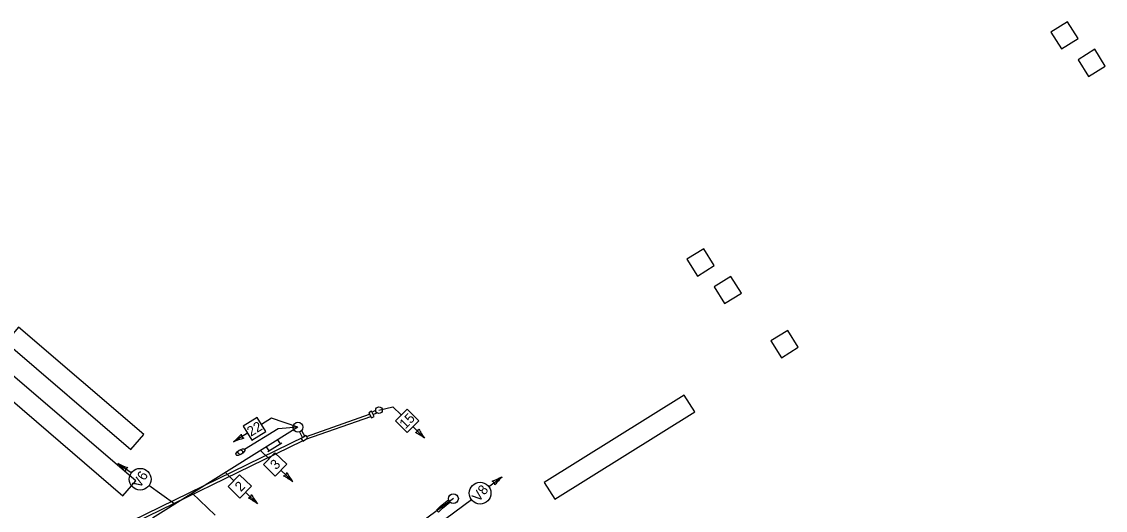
# Model space of a CAD drawing. Extents: x 982100 to 1292532, y 220574 to 1843876.
# Drawn here: x 984464.9 to 984793.2, y 1843411.6 to 1843559.9 of the extents above; entities that cross this region are included whole.
import ezdxf

# ---------------------------------------------------------------- set-up
doc = ezdxf.new("R2010")
doc.units = 0
for name, color, linetype in [('5', 7, 'Continuous'), ('R_Existing Signal', 7, 'Continuous'), ('R_Existing Signal Mast Arm', 7, 'Continuous'), ('V-SIGNAL-CONDUIT', 7, 'Continuous'), ('V-SIGNAL-HEAD', 7, 'Continuous'), ('V-SIGNAL-LOOP', 7, 'Continuous'), ('V-SIGNAL-MAST', 7, 'Continuous')]:
    doc.layers.add(name, color=color, linetype=linetype)

msp = doc.modelspace()

# ---------------------------------------------------------------- linework, layer by layer
at = {"layer": '5'}
msp.add_line((984548.62, 1843436.87), (984504.52, 1843409.32), dxfattribs=at)
at = {"layer": 'R_Existing Signal'}
for p, q in [((984591.78, 1843412.95), (984590.58, 1843411.68)), ((984592.45, 1843412.32), (984591.78, 1843412.95)), ((984591.84, 1843412.89), (984594.27, 1843414.79)), ((984592.43, 1843412.34), (984594.69, 1843414.11)), ((984590.58, 1843411.68), (984591.25, 1843411.05)), ((984591.25, 1843411.05), (984592.45, 1843412.32))]:
    msp.add_line(p, q, dxfattribs=at)
msp.add_circle((984595.72, 1843415.2), 1.5, dxfattribs=at)
at = {"layer": 'R_Existing Signal Mast Arm'}
msp.add_line((984595.72, 1843415.2), (984568.28, 1843395.12), dxfattribs=at)
msp.add_line((984595.72, 1843415.2), (984568.28, 1843395.12), dxfattribs=at)
at = {"layer": 'V-SIGNAL-CONDUIT'}
for p, q in [((984550.98, 1843433.21), (984570.67, 1843440.09)), ((984551.24, 1843434.09), (984570.33, 1843440.77)), ((984570.9, 1843441.68), (984570.08, 1843441.27)), ((984570.08, 1843441.27), (984570.86, 1843439.71)), ((984570.86, 1843439.71), (984571.68, 1843440.12)), ((984571.68, 1843440.12), (984570.9, 1843441.68)), ((984571.04, 1843441.4), (984572.18, 1843442)), ((984571.4, 1843440.67), (984572.54, 1843441.27)), ((984549.74, 1843435.87), (984550.66, 1843434.09)), ((984466.59, 1843393.05), (984550.6, 1843434.05)), ((984467.04, 1843392.32), (984550.02, 1843432.75)), ((984549.06, 1843435.44), (984549.98, 1843433.66)), ((984551.08, 1843434.35), (984549.59, 1843433.42)), ((984549.59, 1843433.42), (984550.08, 1843432.65)), ((984550.08, 1843432.65), (984551.56, 1843433.57)), ((984551.56, 1843433.57), (984551.08, 1843434.35))]:
    msp.add_line(p, q, dxfattribs=at)
for points in [[(984498.02, 1843430.08), (984501.93, 1843434.63), (984463.99, 1843467.21), (984460.08, 1843462.65)], [(984495.6, 1843416.06), (984499.51, 1843420.62), (984461.57, 1843453.19), (984457.67, 1843448.63)], [(984623.25, 1843420.12), (984626.43, 1843415.03), (984668.84, 1843441.52), (984665.66, 1843446.61)]]:
    msp.add_lwpolyline(points, close=True, dxfattribs=at)
at = {"layer": 'V-SIGNAL-HEAD'}
for p, q in [((984577.37, 1843443.09), (984579.9, 1843440.57)), ((984540.6, 1843439.6), (984537.57, 1843437.71)), ((984542.58, 1843436.42), (984532.47, 1843430.1)), ((984583.45, 1843437.06), (984586.99, 1843433.53)), ((984533.33, 1843435.05), (984529.09, 1843432.41)), ((984537.32, 1843429.81), (984539.88, 1843427.32)), ((984498.12, 1843422.98), (984494.06, 1843425.89)), ((984526.63, 1843423.13), (984529.19, 1843420.64)), ((984543.47, 1843423.83), (984547.05, 1843420.35)), ((984606.46, 1843418.85), (984610.46, 1843421.84)), ((984511.31, 1843413.56), (984503.49, 1843419.15)), ((984516.59, 1843416.86), (984523.51, 1843410.19)), ((984532.77, 1843417.16), (984536.35, 1843413.67)), ((984593.47, 1843409.15), (984601.17, 1843414.9))]:
    msp.add_line(p, q, dxfattribs=at)
for points in [[(984538.89, 1843435.58), (984536.24, 1843439.83), (984532, 1843437.17), (984534.65, 1843432.93)], [(984578.16, 1843438.8), (984581.69, 1843442.35), (984585.23, 1843438.81), (984581.7, 1843435.27)], [(984541.63, 1843429.11), (984538.14, 1843425.53), (984541.72, 1843422.04), (984545.21, 1843425.63)], [(984530.94, 1843422.43), (984527.45, 1843418.85), (984531.03, 1843415.36), (984534.52, 1843418.95)]]:
    msp.add_lwpolyline(points, close=True, dxfattribs=at)
for centre, radius in [((984531.17, 1843429.29), 0.679), ((984500.81, 1843421.07), 3.3), ((984603.81, 1843416.87), 3.3)]:
    msp.add_circle(centre, radius, dxfattribs=at)
for centre, radius, start, end in [((984583.92, 1843436.6), 1.34, 283.2425, 346.9371), ((984606.52, 1843447.98), 24.29, 208.7434, 216.4815), ((984513.27, 1843450.84), 24.29, 310.6242, 318.3623), ((984538.74, 1843410.11), 24.29, 105.6695, 113.4076), ((984532.77, 1843434.71), 1.34, 180.1686, 243.8632), ((984572.61, 1843413.96), 24.29, 53.6981, 61.4363), ((984505.07, 1843447.54), 24.29, 243.0366, 250.7747), ((984477.13, 1843408.47), 24.29, 38.0819, 45.82), ((984497.59, 1843423.36), 1.34, 112.581, 176.2756), ((984543.94, 1843423.38), 1.34, 283.9193, 347.614), ((984566.41, 1843435.02), 24.29, 209.4202, 217.1583), ((984532.9, 1843400.6), 24.29, 54.375, 62.1131), ((984599, 1843443.26), 24.29, 290.3955, 298.1336), ((984606.98, 1843419.24), 1.34, 4.8946, 68.5892), ((984627.74, 1843404.77), 24.29, 135.3502, 143.0884), ((984533.24, 1843416.7), 1.34, 283.9193, 347.614), ((984555.71, 1843428.34), 24.29, 209.4202, 217.1583), ((984522.2, 1843393.92), 24.29, 54.375, 62.1131)]:
    msp.add_arc(centre, radius, start, end, dxfattribs=at)
msp.add_ellipse((984531.17, 1843429.29), major_axis=(1.31, 0.82), ratio=0.441176, dxfattribs=at)
at = {"layer": 'V-SIGNAL-LOOP'}
for points in [[(984785.01, 1843554.78), (984781.83, 1843559.86), (984776.74, 1843556.69), (984779.92, 1843551.6)], [(984793.25, 1843546.4), (984790.07, 1843551.48), (984784.98, 1843548.31), (984788.16, 1843543.22)], [(984674.76, 1843485.9), (984671.58, 1843490.99), (984666.49, 1843487.81), (984669.67, 1843482.72)], [(984683, 1843477.52), (984679.82, 1843482.61), (984674.73, 1843479.43), (984677.91, 1843474.34)], [(984700.22, 1843461.13), (984697.04, 1843466.22), (984691.95, 1843463.04), (984695.13, 1843457.95)]]:
    msp.add_lwpolyline(points, close=True, dxfattribs=at)
at = {"layer": 'V-SIGNAL-MAST'}
for p, q in [((984573.18, 1843442.04), (984577.37, 1843443.09)), ((984548.62, 1843436.87), (984540.6, 1843439.6)), ((984548.62, 1843436.87), (984542.58, 1843436.42)), ((984543.3, 1843431.83), (984542.53, 1843433.06)), ((984539.91, 1843429.71), (984539.14, 1843430.95)), ((984539.48, 1843429.45), (984543.72, 1843432.1))]:
    msp.add_line(p, q, dxfattribs=at)
for centre, radius in [((984573.18, 1843442.04), 1), ((984548.62, 1843436.87), 1.5)]:
    msp.add_circle(centre, radius, dxfattribs=at)

# ---------------------------------------------------------------- texts
at = {"layer": 'V-SIGNAL-HEAD'}
for s, rotation, p in [('15', 45.8538, (984581.2, 1843436.15)), ('22', 32.0571, (984534.36, 1843433.93)), ('3', 45.8538, (984542.01, 1843423.77)), ('V6', 58.5949, (984500.8, 1843418.17)), ('2', 45.8538, (984531.32, 1843417.1)), ('V8', 50.5958, (984603.4, 1843414.01))]:
    msp.add_text(s, height=3, rotation=rotation, dxfattribs=at).set_placement(p)

doc.saveas('drawing.dxf')
